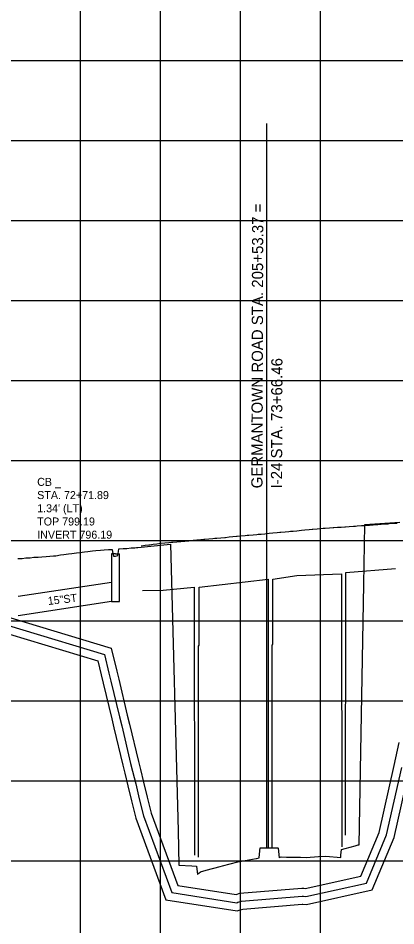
# Model space of a CAD drawing. Extents: x -7164 to 2214450, y -19642 to 253469.
# Drawn here: x 1211 to 1447, y -1741 to -1174 of the extents above; entities that cross this region are included whole.
import ezdxf

# ---------------------------------------------------------------- set-up
doc = ezdxf.new("R2010")
doc.units = 0
for name, color, linetype in [('DESIGN - SHEET - Light Grid', 7, 'Continuous'), ('SURVEY - PROFILE - Drainage - Bridges', 7, 'Continuous'), ('SURVEY - PROFILE - Drainage - Storm Sewer', 7, 'Continuous'), ('SURVEY - PROFILE - Drainage - Storm Sewer Text', 7, 'Continuous'), ('SURVEY - PROFILE - Ground Line with Text', 7, 'Continuous'), ('SURVEY - PROFILE - Utilities - Cable with Text', 7, 'Continuous'), ('SURVEY - PROFILE - Utilities - Electric with Text', 7, 'Continuous')]:
    doc.layers.add(name, color=color, linetype=linetype)

msp = doc.modelspace()

# ---------------------------------------------------------------- linework, layer by layer
at = {"layer": 'DESIGN - SHEET - Light Grid'}
for p, q in [((1250, -3000), (1250, -1000)), ((1250, -3000), (1250, -1000)), ((1300, -3000), (1300, -1000)), ((1300, -3000), (1300, -1000)), ((1350, -3000), (1350, -1000)), ((1350, -3000), (1350, -1000)), ((1400, -3000), (1400, -1000)), ((1400, -3000), (1400, -1000)), ((0, -1200), (12400, -1200)), ((0, -1200), (12400, -1200)), ((0, -1250), (12400, -1250)), ((0, -1250), (12400, -1250)), ((0, -1300), (12400, -1300)), ((0, -1300), (12400, -1300)), ((0, -1350), (12400, -1350)), ((0, -1350), (12400, -1350)), ((0, -1400), (12400, -1400)), ((0, -1400), (12400, -1400)), ((0, -1450), (12400, -1450)), ((0, -1450), (12400, -1450)), ((0, -1500), (12400, -1500)), ((0, -1500), (12400, -1500)), ((0, -1550), (12400, -1550)), ((0, -1550), (12400, -1550)), ((0, -1600), (12400, -1600)), ((0, -1600), (12400, -1600)), ((0, -1650), (12400, -1650)), ((0, -1650), (12400, -1650)), ((0, -1700), (12400, -1700)), ((0, -1700), (12400, -1700))]:
    msp.add_line(p, q, dxfattribs=at)
at = {"layer": 'SURVEY - PROFILE - Drainage - Bridges'}
for points in [[(1287.91, -1503.23), (1289.42, -1503.04), (1290.43, -1502.91), (1292.72, -1502.61), (1293.36, -1502.52), (1295.43, -1502.26), (1297.76, -1501.95), (1300.12, -1501.65), (1300.43, -1501.61), (1302.74, -1501.41), (1305.25, -1501.17), (1306.89, -1501.02), (1307.84, -1500.93), (1310.25, -1500.72), (1312.82, -1500.48), (1313.65, -1500.41), (1315.25, -1500.26), (1317.81, -1500.02), (1320.42, -1499.79), (1322.8, -1499.57), (1325.25, -1499.35), (1327.18, -1499.16), (1327.8, -1499.11), (1330.25, -1498.89), (1332.81, -1498.64), (1333.95, -1498.54), (1335.25, -1498.42), (1337.83, -1498.18), (1340.25, -1497.96), (1340.71, -1497.92), (1342.86, -1497.71), (1345.25, -1497.49), (1347.48, -1497.28), (1347.9, -1497.24), (1350.25, -1497.02), (1352.91, -1496.8), (1354.24, -1496.67), (1355.25, -1496.57), (1357.88, -1496.34), (1360.25, -1496.11), (1361.01, -1496.04), (1362.86, -1495.89), (1365.25, -1495.64), (1367.84, -1495.42), (1370.25, -1495.18), (1372.84, -1494.96), (1374.54, -1494.79), (1375.25, -1494.72), (1377.85, -1494.49), (1380.25, -1494.25), (1381.31, -1494.16), (1382.86, -1494.03), (1385.25, -1493.78), (1388.07, -1493.54), (1390.25, -1493.32), (1392.92, -1493.09), (1394.84, -1492.89), (1395.25, -1492.85), (1397.97, -1492.62), (1400.25, -1492.38), (1401.6, -1492.28), (1402.81, -1492.2), (1405.55, -1492), (1407.81, -1491.85), (1408.37, -1491.81), (1410.56, -1491.65), (1412.81, -1491.5), (1415.13, -1491.33), (1415.58, -1491.29), (1417.81, -1491.14), (1420.61, -1490.94), (1421.9, -1490.85), (1422.81, -1490.79), (1425.64, -1490.58), (1427.8, -1490.43), (1428.66, -1490.37), (1430.69, -1490.22), (1432.8, -1490.07), (1435.43, -1489.88), (1435.74, -1489.85), (1437.79, -1489.71), (1440.8, -1489.49), (1442.19, -1489.39), (1442.79, -1489.35), (1445.87, -1489.12), (1447.78, -1488.99)], [(1287.91, -1503.23), (1289.42, -1503.04), (1290.43, -1502.91), (1292.72, -1502.61), (1293.36, -1502.52), (1295.43, -1502.26), (1297.76, -1501.95), (1300.12, -1501.65), (1300.43, -1501.61), (1302.74, -1501.41), (1305.25, -1501.17), (1306.89, -1501.02), (1307.84, -1500.93), (1310.25, -1500.72), (1312.82, -1500.48), (1313.65, -1500.41), (1315.25, -1500.26), (1317.81, -1500.02), (1320.42, -1499.79), (1322.8, -1499.57), (1325.25, -1499.35), (1327.18, -1499.16), (1327.8, -1499.11), (1330.25, -1498.89), (1332.81, -1498.64), (1333.95, -1498.54), (1335.25, -1498.42), (1337.83, -1498.18), (1340.25, -1497.96), (1340.71, -1497.92), (1342.86, -1497.71), (1345.25, -1497.49), (1347.48, -1497.28), (1347.9, -1497.24), (1350.25, -1497.02), (1352.91, -1496.8), (1354.24, -1496.67), (1355.25, -1496.57), (1357.88, -1496.34), (1360.25, -1496.11), (1361.01, -1496.04), (1362.86, -1495.89), (1365.25, -1495.64), (1367.84, -1495.42), (1370.25, -1495.18), (1372.84, -1494.96), (1374.54, -1494.79), (1375.25, -1494.72), (1377.85, -1494.49), (1380.25, -1494.25), (1381.31, -1494.16), (1382.86, -1494.03), (1385.25, -1493.78), (1388.07, -1493.54), (1390.25, -1493.32), (1392.92, -1493.09), (1394.84, -1492.89), (1395.25, -1492.85), (1397.97, -1492.62), (1400.25, -1492.38), (1401.6, -1492.28), (1402.81, -1492.2), (1405.55, -1492), (1407.81, -1491.85), (1408.37, -1491.81), (1410.56, -1491.65), (1412.81, -1491.5), (1415.13, -1491.33), (1415.58, -1491.29), (1417.81, -1491.14), (1420.61, -1490.94), (1421.9, -1490.85), (1422.81, -1490.79), (1425.64, -1490.58), (1427.8, -1490.43), (1428.66, -1490.37), (1430.69, -1490.22), (1432.8, -1490.07), (1435.43, -1489.88), (1435.74, -1489.85), (1437.79, -1489.71), (1440.8, -1489.49), (1442.19, -1489.39), (1442.79, -1489.35), (1445.87, -1489.12), (1447.78, -1488.99)], [(1415.65, -1684.06), (1415.86, -1519.82), (1446.85, -1517.4)], [(1415.65, -1684.06), (1415.86, -1519.82), (1446.85, -1517.4)], [(1323.7, -1697.69), (1323.78, -1566.01), (1324.19, -1565.39), (1324.2, -1529.02), (1367.2, -1524.07)], [(1323.7, -1697.69), (1323.78, -1566.01), (1324.19, -1565.39), (1324.2, -1529.02), (1367.2, -1524.07)], [(1367.2, -1524.07), (1367.31, -1691.59)], [(1367.2, -1524.07), (1367.31, -1691.59)], [(1369.87, -1691.43), (1369.85, -1565.13), (1370.17, -1564.77), (1370.2, -1524.15), (1385.27, -1521.8), (1413.11, -1520.64)], [(1369.87, -1691.43), (1369.85, -1565.13), (1370.17, -1564.77), (1370.2, -1524.15), (1385.27, -1521.8), (1413.11, -1520.64)], [(1413.11, -1520.64), (1413.23, -1691.35)], [(1413.11, -1520.64), (1413.23, -1691.35)], [(1288.8, -1531.17), (1301.63, -1531), (1321.14, -1529.11)], [(1288.8, -1531.17), (1301.63, -1531), (1321.14, -1529.11)], [(1321.14, -1529.11), (1321.27, -1696.55)], [(1321.14, -1529.11), (1321.27, -1696.55)]]:
    msp.add_lwpolyline(points, dxfattribs=at)
at = {"layer": 'SURVEY - PROFILE - Drainage - Storm Sewer'}
for p, q in [((1271.89, -1508.14), (1269.39, -1508.14)), ((1269.39, -1508.14), (1269.39, -1538.1)), ((1271.89, -1508.14), (1269.39, -1508.14)), ((1269.39, -1508.14), (1269.39, -1538.1)), ((1271.89, -1508.14), (1274.39, -1508.14)), ((1271.89, -1508.14), (1274.39, -1508.14)), ((1274.39, -1538.1), (1274.39, -1508.14)), ((1274.39, -1538.1), (1274.39, -1508.14)), ((1269.4, -1526.1), (1211.13, -1534.9)), ((1269.4, -1526.1), (1211.13, -1534.9)), ((1269.4, -1538.1), (1211.13, -1546.9)), ((1269.4, -1538.1), (1211.13, -1546.9)), ((1269.39, -1538.1), (1274.39, -1538.1)), ((1269.39, -1538.1), (1274.39, -1538.1))]:
    msp.add_line(p, q, dxfattribs=at)
at = {"layer": 'SURVEY - PROFILE - Ground Line with Text'}
msp.add_line((1366.46, -1691.65), (1366.46, -1239.44), dxfattribs=at)
msp.add_line((1366.46, -1691.65), (1366.46, -1239.44), dxfattribs=at)
for points in [[(1274.01, -1505.19), (1276.78, -1504.95), (1279.01, -1504.82), (1281.79, -1504.58), (1284.01, -1504.44), (1284.99, -1504.36), (1285.95, -1504.3), (1306.38, -1502.26), (1311, -1681.23), (1311.55, -1702.74), (1319.66, -1703.16), (1322.43, -1703.34), (1322.89, -1706.88), (1323.12, -1708.59), (1324.01, -1707.77), (1325.07, -1706.82), (1328.67, -1705.89), (1337.3, -1703.64), (1338.85, -1703.22), (1348.27, -1700.71), (1359.7, -1698.51), (1359.92, -1698.47), (1359.94, -1698.47), (1361.69, -1698.1), (1361.94, -1695.81), (1362.38, -1691.96), (1365.18, -1691.94), (1372.03, -1691.86), (1373.03, -1691.84), (1373.44, -1691.84), (1373.48, -1692.17), (1374.13, -1698.09), (1374.41, -1697.99), (1375.44, -1697.62), (1378.73, -1697.65), (1387.49, -1697.8), (1391.09, -1697.89), (1398.76, -1697.27), (1403.42, -1697.05), (1412.62, -1697.93), (1412.79, -1696.43), (1413.19, -1692.89), (1415.49, -1692.3), (1421.6, -1690.62), (1423.48, -1690.11), (1424.19, -1689.94), (1427.03, -1527.48), (1427.68, -1489.89), (1449.53, -1488.35)], [(1274.01, -1505.19), (1276.78, -1504.95), (1279.01, -1504.82), (1281.79, -1504.58), (1284.01, -1504.44), (1284.99, -1504.36), (1285.95, -1504.3), (1306.38, -1502.26), (1311, -1681.23), (1311.55, -1702.74), (1319.66, -1703.16), (1322.43, -1703.34), (1322.89, -1706.88), (1323.12, -1708.59), (1324.01, -1707.77), (1325.07, -1706.82), (1328.67, -1705.89), (1337.3, -1703.64), (1338.85, -1703.22), (1348.27, -1700.71), (1359.7, -1698.51), (1359.92, -1698.47), (1359.94, -1698.47), (1361.69, -1698.1), (1361.94, -1695.81), (1362.38, -1691.96), (1365.18, -1691.94), (1372.03, -1691.86), (1373.03, -1691.84), (1373.44, -1691.84), (1373.48, -1692.17), (1374.13, -1698.09), (1374.41, -1697.99), (1375.44, -1697.62), (1378.73, -1697.65), (1387.49, -1697.8), (1391.09, -1697.89), (1398.76, -1697.27), (1403.42, -1697.05), (1412.62, -1697.93), (1412.79, -1696.43), (1413.19, -1692.89), (1415.49, -1692.3), (1421.6, -1690.62), (1423.48, -1690.11), (1424.19, -1689.94), (1427.03, -1527.48), (1427.68, -1489.89), (1449.53, -1488.35)], [(1211.01, -1511.16), (1213.55, -1511.05), (1216, -1510.77), (1218.58, -1510.67), (1221, -1510.39), (1223.61, -1510.28), (1225.99, -1510.01), (1228.65, -1509.9), (1230.99, -1509.64), (1233.17, -1509.56), (1234.75, -1509.38), (1237.48, -1508.95), (1239.75, -1508.74), (1242.48, -1508.31), (1244.75, -1508.1), (1247.48, -1507.66), (1249.75, -1507.46), (1252.49, -1507.02), (1254.75, -1506.81), (1257.52, -1506.37), (1259.75, -1506.17), (1262.53, -1505.94), (1264.76, -1505.82), (1267.52, -1505.6), (1269.76, -1505.48), (1269.81, -1505.48), (1269.85, -1505.47), (1270.12, -1507.01), (1270.6, -1509.67), (1271.92, -1509.59), (1273.43, -1509.26), (1273.75, -1506.74), (1274.01, -1505.19)], [(1211.01, -1511.16), (1213.55, -1511.05), (1216, -1510.77), (1218.58, -1510.67), (1221, -1510.39), (1223.61, -1510.28), (1225.99, -1510.01), (1228.65, -1509.9), (1230.99, -1509.64), (1233.17, -1509.56), (1234.75, -1509.38), (1237.48, -1508.95), (1239.75, -1508.74), (1242.48, -1508.31), (1244.75, -1508.1), (1247.48, -1507.66), (1249.75, -1507.46), (1252.49, -1507.02), (1254.75, -1506.81), (1257.52, -1506.37), (1259.75, -1506.17), (1262.53, -1505.94), (1264.76, -1505.82), (1267.52, -1505.6), (1269.76, -1505.48), (1269.81, -1505.48), (1269.85, -1505.47), (1270.12, -1507.01), (1270.6, -1509.67), (1271.92, -1509.59), (1273.43, -1509.26), (1273.75, -1506.74), (1274.01, -1505.19)]]:
    msp.add_lwpolyline(points, dxfattribs=at)
at = {"layer": 'SURVEY - PROFILE - Utilities - Cable with Text'}
msp.add_lwpolyline([(1161.29, -1545.13), (1260.88, -1575.01), (1262.97, -1583.88), (1264.2, -1588.97), (1269.6, -1611.27), (1270.95, -1616.89), (1276.54, -1640.29), (1277.74, -1645.22), (1279.67, -1653.19), (1281.94, -1662.56), (1284.6, -1673.28), (1303.46, -1724.33), (1348.03, -1731.28), (1349.82, -1730.71), (1351.55, -1730.16), (1388.51, -1727.13), (1388.95, -1727.16), (1391.2, -1727.33), (1432.35, -1718.23), (1446.1, -1685.36), (1455.67, -1642.77)], dxfattribs=at)
msp.add_lwpolyline([(1161.29, -1545.13), (1260.88, -1575.01), (1262.97, -1583.88), (1264.2, -1588.97), (1269.6, -1611.27), (1270.95, -1616.89), (1276.54, -1640.29), (1277.74, -1645.22), (1279.67, -1653.19), (1281.94, -1662.56), (1284.6, -1673.28), (1303.46, -1724.33), (1348.03, -1731.28), (1349.82, -1730.71), (1351.55, -1730.16), (1388.51, -1727.13), (1388.95, -1727.16), (1391.2, -1727.33), (1432.35, -1718.23), (1446.1, -1685.36), (1455.67, -1642.77)], dxfattribs=at)
at = {"layer": 'SURVEY - PROFILE - Utilities - Electric with Text'}
for points in [[(1163.63, -1535.39), (1269.29, -1567.09), (1272.69, -1581.56), (1273.92, -1586.62), (1279.32, -1608.93), (1280.67, -1614.57), (1286.26, -1637.95), (1287.45, -1642.86), (1289.39, -1650.84), (1291.66, -1660.18), (1294.17, -1670.33), (1310.81, -1715.36), (1347.24, -1721.04), (1349.6, -1720.29), (1388.43, -1717.11), (1389.65, -1717.19), (1390.48, -1717.25), (1425.13, -1709.59), (1436.54, -1682.31), (1445.92, -1640.56), (1449.22, -1626.08)], [(1163.63, -1535.39), (1269.29, -1567.09), (1272.69, -1581.56), (1273.92, -1586.62), (1279.32, -1608.93), (1280.67, -1614.57), (1286.26, -1637.95), (1287.45, -1642.86), (1289.39, -1650.84), (1291.66, -1660.18), (1294.17, -1670.33), (1310.81, -1715.36), (1347.24, -1721.04), (1349.6, -1720.29), (1388.43, -1717.11), (1389.65, -1717.19), (1390.48, -1717.25), (1425.13, -1709.59), (1436.54, -1682.31), (1445.92, -1640.56), (1449.22, -1626.08)], [(1162.85, -1540.38), (1265.09, -1571.05), (1265.09, -1571.05), (1267.83, -1582.72), (1269.06, -1587.79), (1274.46, -1610.1), (1275.81, -1615.73), (1281.4, -1639.12), (1282.6, -1644.04), (1284.53, -1652.02), (1286.8, -1661.37), (1289.39, -1671.81), (1307.13, -1719.84), (1347.64, -1726.16), (1348.3, -1725.95), (1350.57, -1725.22), (1388.47, -1722.12), (1389.3, -1722.17), (1390.84, -1722.29), (1428.74, -1713.91), (1441.32, -1683.83), (1450.79, -1641.67)], [(1162.85, -1540.38), (1265.09, -1571.05), (1265.09, -1571.05), (1267.83, -1582.72), (1269.06, -1587.79), (1274.46, -1610.1), (1275.81, -1615.73), (1281.4, -1639.12), (1282.6, -1644.04), (1284.53, -1652.02), (1286.8, -1661.37), (1289.39, -1671.81), (1307.13, -1719.84), (1347.64, -1726.16), (1348.3, -1725.95), (1350.57, -1725.22), (1388.47, -1722.12), (1389.3, -1722.17), (1390.84, -1722.29), (1428.74, -1713.91), (1441.32, -1683.83), (1450.79, -1641.67)]]:
    msp.add_lwpolyline(points, dxfattribs=at)

# ---------------------------------------------------------------- texts
at = {"layer": 'SURVEY - PROFILE - Drainage - Storm Sewer Text'}
for s, p in [('CB _', (1223.02, -1465.77)), ('CB _', (1223.02, -1465.77)), ('STA. 72+71.89', (1223.02, -1474.02)), ('STA. 72+71.89', (1223.02, -1474.02)), ("1.34' (LT)", (1223.02, -1482.27)), ("1.34' (LT)", (1223.02, -1482.27)), ('TOP 799.19', (1223.02, -1490.52)), ('TOP 799.19', (1223.02, -1490.52)), ('INVERT 796.19', (1223.02, -1498.77)), ('INVERT 796.19', (1223.02, -1498.77))]:
    msp.add_text(s, height=5, dxfattribs=at).set_placement(p)
msp.add_text('15"ST', height=5, rotation=6.6474, dxfattribs=at).set_placement((1229.92, -1540.23))
msp.add_text('15"ST', height=5, rotation=6.6474, dxfattribs=at).set_placement((1229.92, -1540.23))
at = {"layer": 'SURVEY - PROFILE - Ground Line with Text'}
for s, p in [('GERMANTOWN ROAD STA. 205+53.37 =', (1363.76, -1467.33)), ('GERMANTOWN ROAD STA. 205+53.37 =', (1363.76, -1467.33)), ('I-24 STA. 73+66.46', (1376.01, -1467.37)), ('I-24 STA. 73+66.46', (1376.01, -1467.37))]:
    msp.add_text(s, height=7, rotation=89.8304, dxfattribs=at).set_placement(p)

doc.saveas('drawing.dxf')
